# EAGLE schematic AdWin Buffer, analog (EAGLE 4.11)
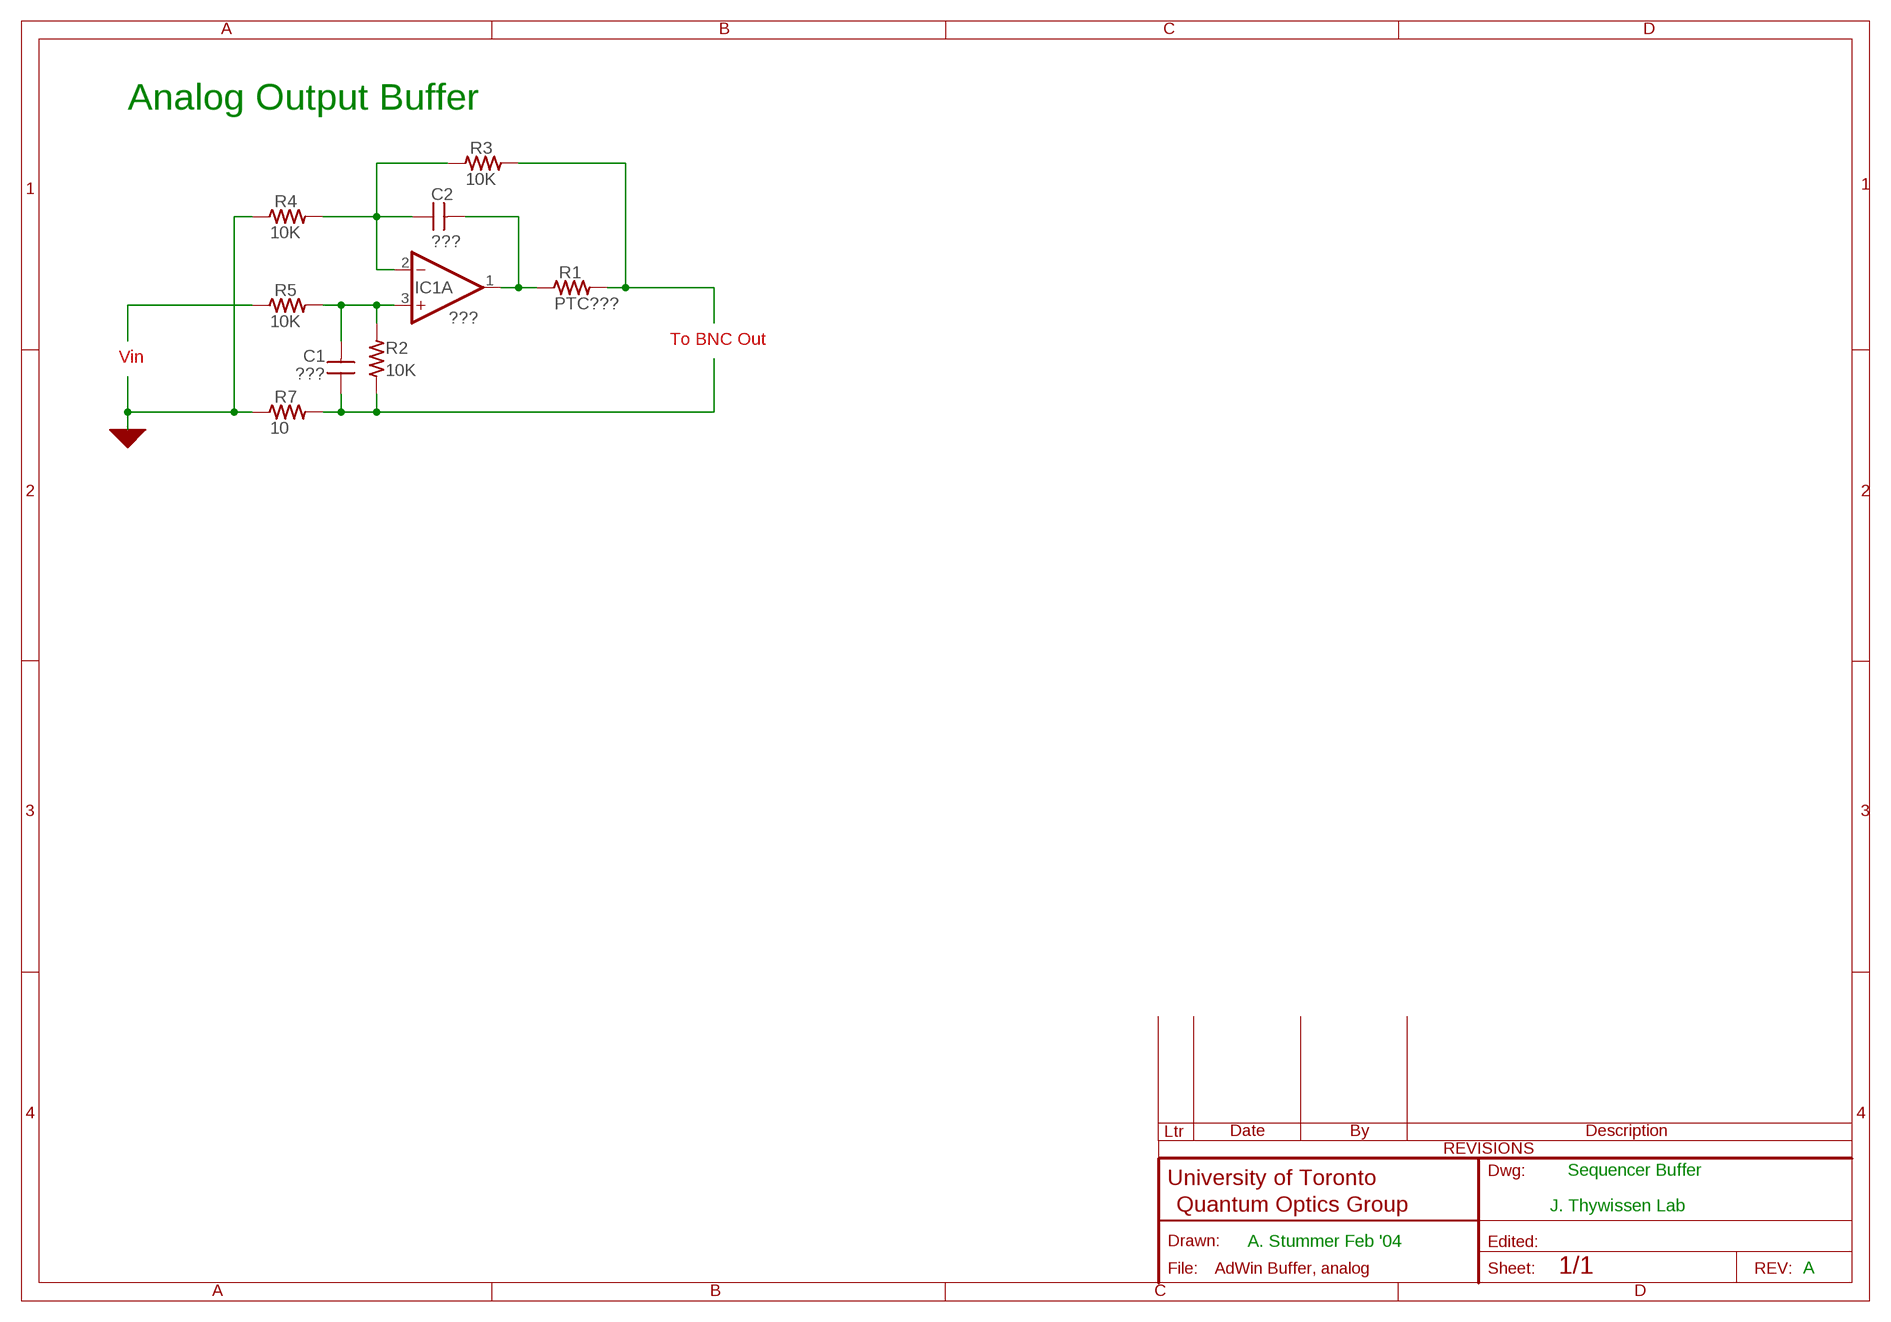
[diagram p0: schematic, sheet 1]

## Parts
C1  ???  CAP-V-0805  [0805]
C2  ???  CAP-H-0805  [0805]
IC1  ???  LM324D  [SOIC-14]
R1  PTC???  R-H-0805  [0805]
R2  10K  R-V-0805  [0805]
R3  10K  R-H-0805  [0805]
R4  10K  R-H-0805  [0805]
R5  10K  R-H-0805  [0805]
R7  10  R-H-0805  [0805]

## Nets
AGND: R4.1 R7.1
N$1: C2.1 IC1.1(A:OUT) R1.1
N$2: R1.2 R3.2
N$3: C2.2 IC1.2(A:-IN) R3.1 R4.2
N$4: R5.1
N$5: C1.2 IC1.3(A:+IN) R2.2 R5.2
N$7: C1.1 R2.1 R7.2
Unconnected: IC1.4(V+) IC1.5(B:+IN) IC1.6(B:-IN) IC1.7(B:OUT) IC1.8(C:OUT) IC1.9(C:-IN) IC1.10(C:+IN) IC1.11(V-) IC1.12(D:+IN) IC1.13(D:-IN) IC1.14(D:OUT)

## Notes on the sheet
- Analog Output Buffer
- To BNC Out
- Vin
- Sequencer Buffer
- J. Thywissen Lab
- A. Stummer Feb '04
- A

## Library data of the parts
C1 = 0-UofT-Physics:CAP-V-: Cap, SMT, 0402 to 1206
C2 = 0-UofT-Physics:CAP-H-: Cap, SMT, 0402 to 1206
IC1 = 0-UofT-Physics:LM324: OP AMP
R1 R3-R5 R7 = 0-UofT-Physics:R-H-*: Resistor, SMT, horizontal symbol
R2 = 0-UofT-Physics:R-V-*: Resistor, SMT, vertical symbol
